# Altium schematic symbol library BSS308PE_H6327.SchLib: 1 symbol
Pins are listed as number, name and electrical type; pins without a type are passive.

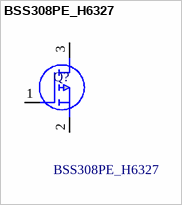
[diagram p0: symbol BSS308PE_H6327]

## BSS308PE_H6327
designator Q?
MOSFET P-Ch -30V -2A SOT-23-3; Manufacturer_Name: Infineon; Manufacturer_Part_Number: BSS308PE H6327; Geometry.Height: 1.1mm
footprint SOT95P260X110-3N
pins: 1 G, 2 S, 3 D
